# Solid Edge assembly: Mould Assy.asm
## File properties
Author: Dave
Template: normal.asm
Last saved by: Dave
Revision: 16
Application: Solid Edge
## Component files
MH Die Plate.par
MH Insert.par
FH Die Plate.par
FH Insert.par
Support Plate .par
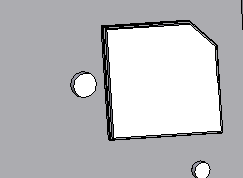
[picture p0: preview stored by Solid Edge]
